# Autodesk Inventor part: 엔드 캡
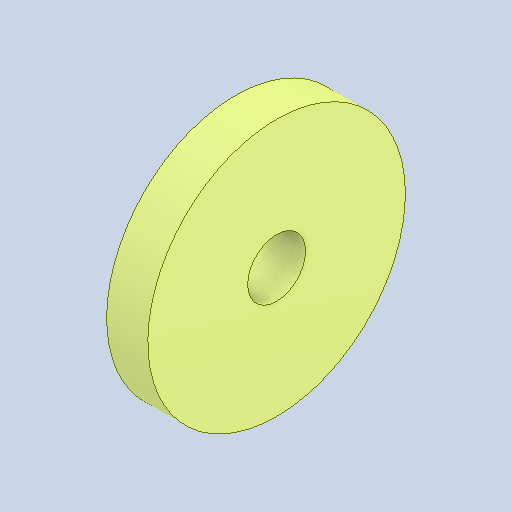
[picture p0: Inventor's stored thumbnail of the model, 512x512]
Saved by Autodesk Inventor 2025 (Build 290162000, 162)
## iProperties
Created: 2026-03
Part Number: 엔드 캡
Material: 강철, 연강
Document SubType Name: Modeling
Designer: KDI
Density: 7.85 g/cm^3
Appearance: 기본값
Author: jhkim
Sending System: Autodesk Inventor 2026
Preprocessor: ST-DEVELOPER v20.1
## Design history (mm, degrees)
feature "솔리드1"
node "솔리드2"
